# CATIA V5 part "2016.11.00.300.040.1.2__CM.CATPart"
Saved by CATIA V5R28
Part number: 2016.11.00.300.040.1.2__CM
Property "id_number": "2016.11.00.300.040.1.2"
Publications: "Absolute Axis System", "driver", "slider", "base", "cam diagram"
Bounding box of the stored display mesh (mm): x -40 to 210, y -205 to 205, z 0 to 310
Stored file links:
  N:\B2\Normteile\K\2016\11-14\030\cm\2016.11.00.300.040.1.2__CM.CATPart
  H:\CAD_Startmodelle\Tests\fill-in_PRT-SL_TEMPLATE.xlsx
  H:\CAD_Startmodelle\V5-R24\R24_TEMPLATE_PRT_FIBRO_CAM_TECNOLOGIES_INDEX.xlsx
  H:\z_Einordnen\170511__Anfrage_TK_HN\170511__CC01_TKHN.CATPart
  N:\B2\Normteile\K\2016\9xxx\2016.9024.1705.001\Entwurf_\170511__CC01_TKHN.CATPart
  N:\B2\Normteile\K\2016\9xxx\2016.9024.1707.006\Konstruktion\2016.9024.1707.006__HP__CUSTOMIZED_CAM_CM.CATPart
  N:\B2\Normteile\K\2016\9xxx\2016.9024.1707.005\Konstruktion\2016.9024.1707.005__HP__CUSTOMIZED_CAM_CM.CATPart
  N:\B2\Normteile\K\2016\9xxx\2016.9024.1707.008\Konstruktion\2016.9024.1707.008__HP__CUSTOMIZED_CAM_CM.CATPart
  N:\B2\Normteile\K\2016\9xxx\2016.9024.1707.009\Konstruktion\2016.9024.1707.009__HP__CUSTOMIZED_CAM_CM.CATPart
  N:\B2\Normteile\K\2016\9xxx\2016.9024.1707.010\Konstruktion\2016.9024.1707.010__HP__CUSTOMIZED_CAM_CM.CATPart
  N:\B2\Normteile\K\2016\9xxx\2016.9024.1708.002\Konstruktion\2016.9024.1708.002__HP__CUSTOMIZED_CAM_CM.CATPart
  N:\B2\Normteile\K\2016\9xxx\2016.9024.1802.001\Konstruktion\2016.9024.1802.001__HP__CUSTOMIZED_CAM_CM.CATPart
  N:\B2\Normteile\K\2016\9xxx\2016.9024.1802.002\Konstruktion\2016.9024.1802.002__HP__CUSTOMIZED_CAM_CM.CATPart
  N:\B2\Normteile\K\2016\9xxx\2016.9024.1811.003\Konstruktion\2016.9024.1811.003__HP__CUSTOMIZED_CAM_CM.CATPart
  N:\B2\Normteile\K\2016\9xxx\2016.9015.1811.001\Konstruktion\am\2016.9015.1811.001__AM__FCC_HV_DMC_0125-00.CATPart
  N:\B2\Normteile\K\2016\9xxx\2016.9024.1811.009\Konstruktion\2016.9024.1811.009__HP__CUSTOMIZED_CAM_CM.CATPart
  N:\B2\Normteile\K\2016\9xxx\2016.9024.1911.002\Konstruktion\am\2016.9024.1911.002__AM__CUSTOMIZED_CAM_CM.CATPart
  N:\B2\Normteile\K\2016\9xxx\2016.9024.2002.006\Konstruktion\2016.9024.2002.006__AM.CATPart
  N:\B2\Normteile\K\2016\9xxx\2016.9024.2004.001\Konstruktion\2016.9024.2004.001__AM__FCC_HV_CAEC_0260-45.CATPart
  N:\B2\Normteile\K\2016\9xxx\2016.9024.2006.002\Konstruktion\2016.9024.2006.002__AM__FCC_HV_CAEC_0260-40.CATPart
  N:\B2\Normteile\K\2016\9xxx\2016.9024.2006.005\Konstruktion\am\2016.9024.2006.005__AM__CFCC_HV_AEPC_0080-65.CATPart
  N:\B2\Normteile\K\2016\9xxx\2016.9024.2006.004\Konstruktion\am\2016.9024.2006.004__AM__CFCC_HV_AEC_0210-35.CATPart
  N:\B2\Normteile\K\2016\9xxx\2016.9026.2006.001\Konstruktion\am\2016.9026.2006.001__AM__FCC_LV_CAEC_0180-40.CATPart
  N:\B2\Normteile\K\2016\9xxx\2016.9015.2007.001\Konstruktion\am\2016.9015.2007.001__AM__FCC_HV_CDMPC_0090-00.CATPart
  N:\B2\Normteile\K\2016\9xxx\2016.9024.2005.001\Konstruktion\am\2016.9024.2005.001__AM__CFCC_HV_AEPC_1400-70.CATPart
  N:\B2\Normteile\K\2016\9xxx\2016.9024.2007.004\Konstruktion\am\2016.9024.2007.004__AM__CFCC_HV_AEC_1250-80.CATPart
  N:\B2\Normteile\K\2016\11-14\005\2016.11.00.052.040.1.02__AS__DIE_MOUNT_CAM__W52_A0_S40.CATProduct
  N:\B2\Normteile\K\2016\11-14\015\2016.11.00.150.060.1.02__AS__DIE_MOUNT_CAM__W150_A0_S60.CATProduct
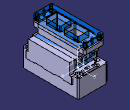
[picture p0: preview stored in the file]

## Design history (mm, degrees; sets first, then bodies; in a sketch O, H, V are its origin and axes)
Parameters
  group "process_parameters"
    modeltype = ""
    stocklist = ""
    id_number = "2016.11.00.300.040.1.2"
    id_number_rough_part = ""
    revision_index = ""
    revision_date = ""
    revision_description = ""
    category = ""
    material = ""
    manufacturing_information = ""
    standard = ""
  group "release_parameters_startmodel"
    sm_revision_index = "2016_00" {design table}
    sm_revision_date = "20.08.2016" {design table}
    sm_revision_name = "Meyer" {design table}
    sm_revision_description = "new part template FIBRO cam tecnologies" {design table}
AxisSystem1: origin (0, 0, 0), X (1, 0, 0), Y (0, 1, 0), Z (0, 0, 1)
Set1 "reference elements"
  Sketch1 "cam diagram" on ZX plane of AxisSystem1, origin (0, 0, 0), H (-1, 0, 0), V (0, 0, 1)
    line L1 (0, 0) -> (40, 0)
    line L2 (40, 0) -> (0, 40)
    point P2 (0, 40)
    line L3 (0, 40) -> (0, 0)
    length L1 = 40
    angle H L2 = 45
    horizontal: L1 H
    coincidence: P2 V
    vertical: L3 V
Body1 "finished_part" (main body)
  Body2 "rough_part"
  Add1 "rough_part": tool Body2
  Body3 "milling operations"
  Remove1 "milling operations": tool Body3
  Body4 "drilling operations"
  Remove2 "drilling operations": tool Body4
Body5 "driver"
  Solid1: solid without history
Body6 "slider"
  Solid2: solid without history
Body7 "base"
  Solid3: solid without history
Body8 "opened position"
  Body9 "slider"
    Body10 "slider"
      Solid4: linked copy from another document
    Assemble1: tool Body10
    Translate1: FirstPoint vertex [element of Sketch1 | element of Sketch1], SecondPoint vertex [element of Sketch1 | element of Sketch1], ToTransfor Assemble1
  Assemble2: tool Body9
  Body11 "driver"
    Body12 "driver"
      Solid5: linked copy from another document
    Assemble3: tool Body12
    Translate2: FirstPoint vertex [element of Sketch1 | element of Sketch1], SecondPoint vertex [element of Sketch1 | element of Sketch1], ToTransfor Assemble3
  Assemble4: tool Body11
